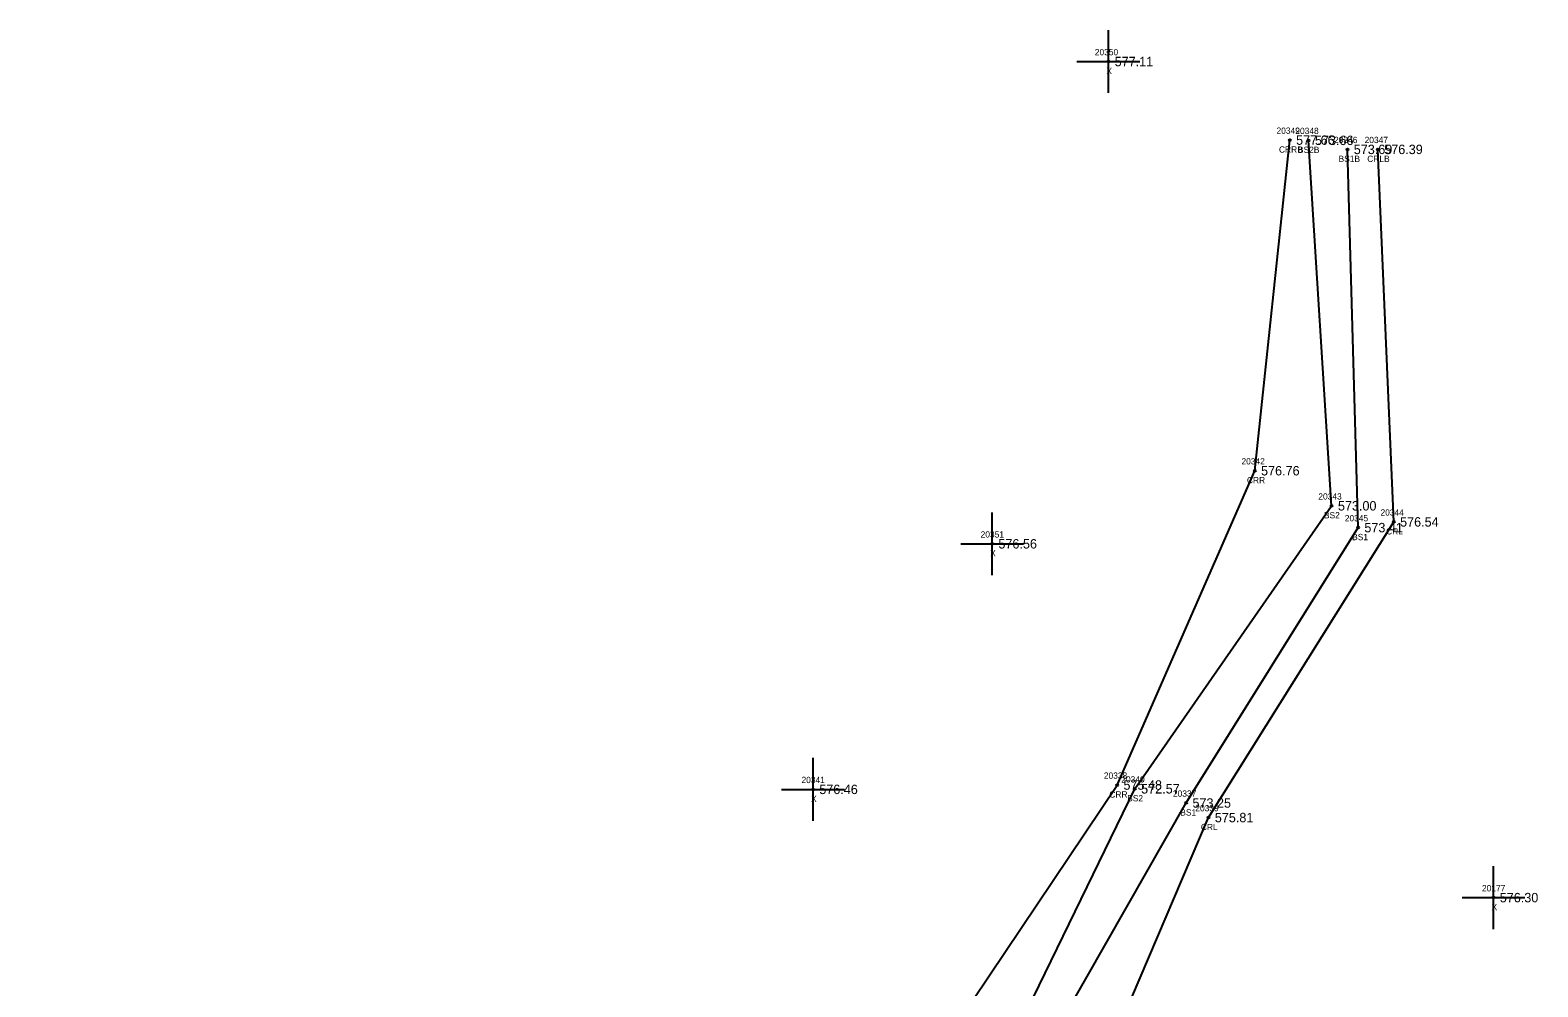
# Model space of a CAD drawing. Extents: x 1664837 to 1666270, y 987403 to 988245.
# Drawn here: x 1665511.2 to 1665751.3, y 988092.7 to 988245.1 of the extents above; entities that cross this region are included whole.
import ezdxf

# ---------------------------------------------------------------- set-up
doc = ezdxf.new("R2010")
doc.units = 0
for name, color, linetype in [('RD_DTM_BkLn2', 7, 'Continuous'), ('RD_DTM_BkLn_txCode', 7, 'Continuous'), ('RD_EX_H2O', 7, 'Continuous'), ('RD_EX_H2O_txCode', 7, 'Continuous'), ('RD_EX_Misc', 7, 'Continuous'), ('RD_EX_Misc_txCode', 7, 'Continuous'), ('RD_EX_TX_H2O_ELEV', 7, 'Continuous'), ('RD_EX_TX_Misc_ELEV', 7, 'Continuous'), ('RD_SMD_Locator', 7, 'Continuous')]:
    doc.layers.add(name, color=color, linetype=linetype)

msp = doc.modelspace()

# ---------------------------------------------------------------- linework, layer by layer
at = {"layer": 'RD_DTM_BkLn2'}
for points in [[(1665511.23, 987778.14), (1665517.66, 987789.45), (1665551.13, 987799.55), (1665566.94, 987815.17), (1665584.37, 987828.05), (1665587.06, 987846.74), (1665590.03, 987866.53), (1665606.32, 987897.21), (1665626.52, 987926.63), (1665648.51, 987960.46), (1665641.85, 987993.37), (1665649.56, 988007.84), (1665641.39, 988045.42), (1665662.4, 988073.33), (1665687.13, 988124.22), (1665718.46, 988169.29), (1665714.8, 988227.5)], [(1665573.38, 987803.15), (1665572.7, 987806.28), (1665588.73, 987824.67), (1665594.9, 987842.89), (1665595.52, 987863.7), (1665620.34, 987892.03), (1665633.86, 987922.65), (1665655.32, 987971.56), (1665650.57, 987994.06), (1665655.98, 988006.97), (1665652.16, 988045.8), (1665666.56, 988071.61), (1665695.3, 988121.96), (1665722.67, 988165.82), (1665720.98, 988226.06)]]:
    msp.add_lwpolyline(points, dxfattribs=at)
at = {"layer": 'RD_EX_H2O'}
for points in [[(1665526.5, 987797.57), (1665535.59, 987808.2), (1665547.98, 987825.42), (1665568.59, 987829.69), (1665585.83, 987856.79), (1665584.87, 987866.91), (1665603.81, 987898.8), (1665618.99, 987930.85), (1665645.33, 987961.5), (1665639.67, 987994.37), (1665644.94, 988008.07), (1665639.5, 988048.94), (1665653.76, 988079.25), (1665684.31, 988124.82), (1665706.22, 988174.88), (1665711.8, 988227.54)], [(1665576.75, 987805.68), (1665589.55, 987821.56), (1665609.09, 987853.11), (1665622.95, 987890.58), (1665641.35, 987920.45), (1665654.29, 987935.19), (1665658.75, 987952.97), (1665657.67, 987971.74), (1665650.8, 987993.69), (1665662.98, 988008.61), (1665660.68, 988035.04), (1665652.89, 988045.21), (1665674.32, 988062.08), (1665698.86, 988119.64), (1665728.36, 988166.73), (1665725.83, 988226.06)]]:
    msp.add_lwpolyline(points, dxfattribs=at)
at = {"layer": 'RD_EX_Misc'}
for p, q in [((1665682.91, 988235.05), (1665682.91, 988245.05)), ((1665677.91, 988240.05), (1665687.91, 988240.05)), ((1665664.4, 988158.24), (1665664.4, 988168.24)), ((1665659.4, 988163.24), (1665669.4, 988163.24)), ((1665635.88, 988119.13), (1665635.88, 988129.13)), ((1665630.88, 988124.13), (1665640.88, 988124.13)), ((1665744.23, 988101.89), (1665744.23, 988111.89)), ((1665739.23, 988106.89), (1665749.23, 988106.89))]:
    msp.add_line(p, q, dxfattribs=at)
at = {"layer": 'RD_SMD_Locator'}
for centre in [(1665682.91, 988240.05), (1665711.8, 988227.54), (1665714.8, 988227.5), (1665720.98, 988226.06), (1665725.83, 988226.06), (1665706.22, 988174.88), (1665718.46, 988169.29), (1665722.67, 988165.82), (1665728.36, 988166.73), (1665664.4, 988163.24), (1665635.88, 988124.13), (1665684.31, 988124.82), (1665687.13, 988124.22), (1665695.3, 988121.96), (1665698.86, 988119.64), (1665744.23, 988106.89)]:
    msp.add_circle(centre, 0.15, dxfattribs=at)

# ---------------------------------------------------------------- texts
at = {"layer": 'RD_DTM_BkLn_txCode'}
for s, p in [('20348', (1665712.68, 988228.5)), ('BS2B', (1665713.09, 988225.5)), ('20346', (1665718.84, 988227.06)), ('BS1B', (1665719.56, 988224.06)), ('20343', (1665716.34, 988170.29)), ('BS2', (1665717.23, 988167.29)), ('20345', (1665720.55, 988166.82)), ('BS1', (1665721.72, 988163.82)), ('20340', (1665684.97, 988125.22)), ('BS2', (1665685.9, 988122.22)), ('20337', (1665693.19, 988122.96)), ('BS1', (1665694.36, 988119.96))]:
    msp.add_text(s, height=1, dxfattribs=at).set_placement(p)
at = {"layer": 'RD_EX_H2O_txCode'}
for s, p in [('20349', (1665709.68, 988228.54)), ('CRRB', (1665710.07, 988225.54)), ('20347', (1665723.71, 988227.06)), ('CRLB', (1665724.13, 988224.06)), ('20342', (1665704.1, 988175.88)), ('CRR', (1665704.97, 988172.88)), ('20344', (1665726.24, 988167.73)), ('CRL', (1665727.13, 988164.73)), ('20338', (1665682.19, 988125.82)), ('CRR', (1665683.06, 988122.82)), ('20339', (1665696.75, 988120.64)), ('CRL', (1665697.64, 988117.64))]:
    msp.add_text(s, height=1, dxfattribs=at).set_placement(p)
at = {"layer": 'RD_EX_Misc_txCode'}
for s, p in [('20350', (1665680.75, 988241.05)), ('X', (1665682.6, 988238.05)), ('20351', (1665662.57, 988164.24)), ('X', (1665664.09, 988161.24)), ('20341', (1665634.05, 988125.13)), ('X', (1665635.57, 988122.13)), ('20177', (1665742.4, 988107.89)), ('X', (1665743.92, 988104.89))]:
    msp.add_text(s, height=1, dxfattribs=at).set_placement(p)
at = {"layer": 'RD_EX_TX_H2O_ELEV'}
for s, p in [('577.66', (1665712.8, 988226.79)), ('576.39', (1665726.83, 988225.31)), ('576.76', (1665707.22, 988174.13)), ('576.54', (1665729.36, 988165.98)), ('575.48', (1665685.31, 988124.07)), ('575.81', (1665699.86, 988118.89))]:
    msp.add_text(s, height=1.5, dxfattribs=at).set_placement(p)
at = {"layer": 'RD_EX_TX_Misc_ELEV'}
for s, p in [('577.11', (1665683.91, 988239.3)), ('573.66', (1665715.8, 988226.75)), ('573.69', (1665721.98, 988225.31)), ('573.00', (1665719.46, 988168.54)), ('573.41', (1665723.67, 988165.07)), ('576.56', (1665665.4, 988162.49)), ('572.57', (1665688.13, 988123.47)), ('576.46', (1665636.88, 988123.38)), ('573.25', (1665696.3, 988121.21)), ('576.30', (1665745.23, 988106.14))]:
    msp.add_text(s, height=1.5, dxfattribs=at).set_placement(p)

doc.saveas('drawing.dxf')
